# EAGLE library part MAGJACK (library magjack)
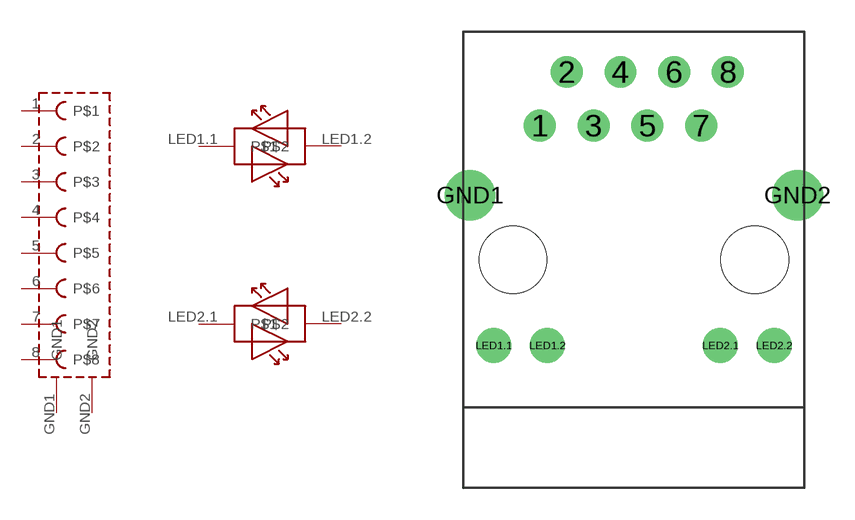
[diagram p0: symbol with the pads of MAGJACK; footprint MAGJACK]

Designator prefix -; gates G$1=MAGJACK G$2=LED G$3=LED

## MAGJACK  [MAGJACK]
1  G$1:P$1  pas
2  G$1:P$2  pas
3  G$1:P$3  pas
4  G$1:P$4  pas
5  G$1:P$5  pas
6  G$1:P$6  pas
7  G$1:P$7  pas
8  G$1:P$8  pas
GND1  G$1:GND1  pas
GND2  G$1:GND2  pas
LED1.1  G$2:P$1  pas
LED1.2  G$2:P$2  pas
LED2.1  G$3:P$1  pas
LED2.2  G$3:P$2  pas

## Footprint MAGJACK (pad centres in mm)
drill 1 round: 1 -4.445,6.35; 2 -3.175,8.89; 3 -1.905,6.35; 4 -0.635,8.89; 5 0.635,6.35; 6 1.905,8.89; 7 3.175,6.35; 8 4.445,8.89
drill 1.6 round: GND1 -7.747,3.048; GND2 7.747,3.048
drill 1.1 round: LED1.1 -6.629,-4.064; LED1.2 -4.089,-4.064; LED2.1 4.089,-4.064; LED2.2 6.629,-4.064
hole 3.2 at -5.715,0
hole 3.2 at 5.715,0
